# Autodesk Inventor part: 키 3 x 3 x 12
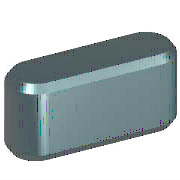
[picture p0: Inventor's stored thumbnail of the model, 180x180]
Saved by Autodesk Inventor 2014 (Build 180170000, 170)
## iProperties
Created: 2012-02
Part Number: 키 3 x 3 x 12
Material: 강철, 연강
Description: 키 및 해당 키홈
Document SubType Name: Modeling
Standard: KS B 1311
Designer: mduedu
Standards Organization: KS
Language: ko-KR
Size Designation: 3 x 3 x 12
Categories: <MemberInstance><Categories><Category DisplayName="샤프트 부품" InternalName="7f7aeb1f-a693-4053-b835-cee3144e0d98" Mnemonic="SHFT"><Category DisplayName="키" Interna
Density: 1 g/cm^3
Appearance: Yellow
IsCustomPart: 1
Author: mduedu
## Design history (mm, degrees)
sketch "스케치1"
  geometry: L1 (1.5, 1.5)-(10.5, 1.5); L2 (10.5, -1.5)-(1.5, -1.5); L3 (0, 9.4)-(0, -7.4) reference; L4 (-5, 0)-(30, 0) reference; L5 (12, 0)-(12, 7); A1 r 1.5 centre (1.5, 0) between (1.5, 1.5) and (1.5, -1.5); A2 r 1.5 centre (10.5, 0) between (10.5, -1.5) and (10.5, 1.5)
  constraints: 6 end point, 5 point on circle, 4 tangent, 3 point on line, 2 centre point, 1 horizontal, 1 parallel, 1 perpendicular
  dimensions: "d0" = 1.5 radius of A1 (= 0.5 x PB); "d13" = 1.5 radius of A2 (= 0.5 x PB); "d14" = 12 distance between parallel lines of L5 L3 (= NLG)
extrude "본체1" new body sketch "스케치1" taper "d3" = 0 deg; stored distance "d4" = 10
workplane "Work Plane3"
body "Solid1"
workplane "Work Plane1"
workplane "Work Plane2"
chamfer "모따기1" distance "d8" = 0.25 (= PHH); stored, may be unused: second distance "d9" = 0.25 (= PHH), angle "d15" = 45 deg
other parameters: "d1" = -1.8 (= -PNT), "d2" = 1.2 (= PH - PNT), "NLG" = 12 [user parameter; used in 3 equation terms], "PB" = 3 [user parameter; used in 2 equation terms], "PNT" = 1.8 [user parameter; used in 2 equation terms], "PH" = 3 [user parameter; used in 1 equation term], "PHH" = 0.25 [user parameter; used in 2 equation terms], "d10" = 0, "d16" = 0, "d17" = 0, "d18" = 0, "WDMIN" = 8 [user parameter], "PLB2" = 12 (= NLG) [user parameter], "PLB1" = 12 (= NLG) [user parameter], "RR" = 0.08 [user parameter], "PUEB" = 1.4 [user parameter]
